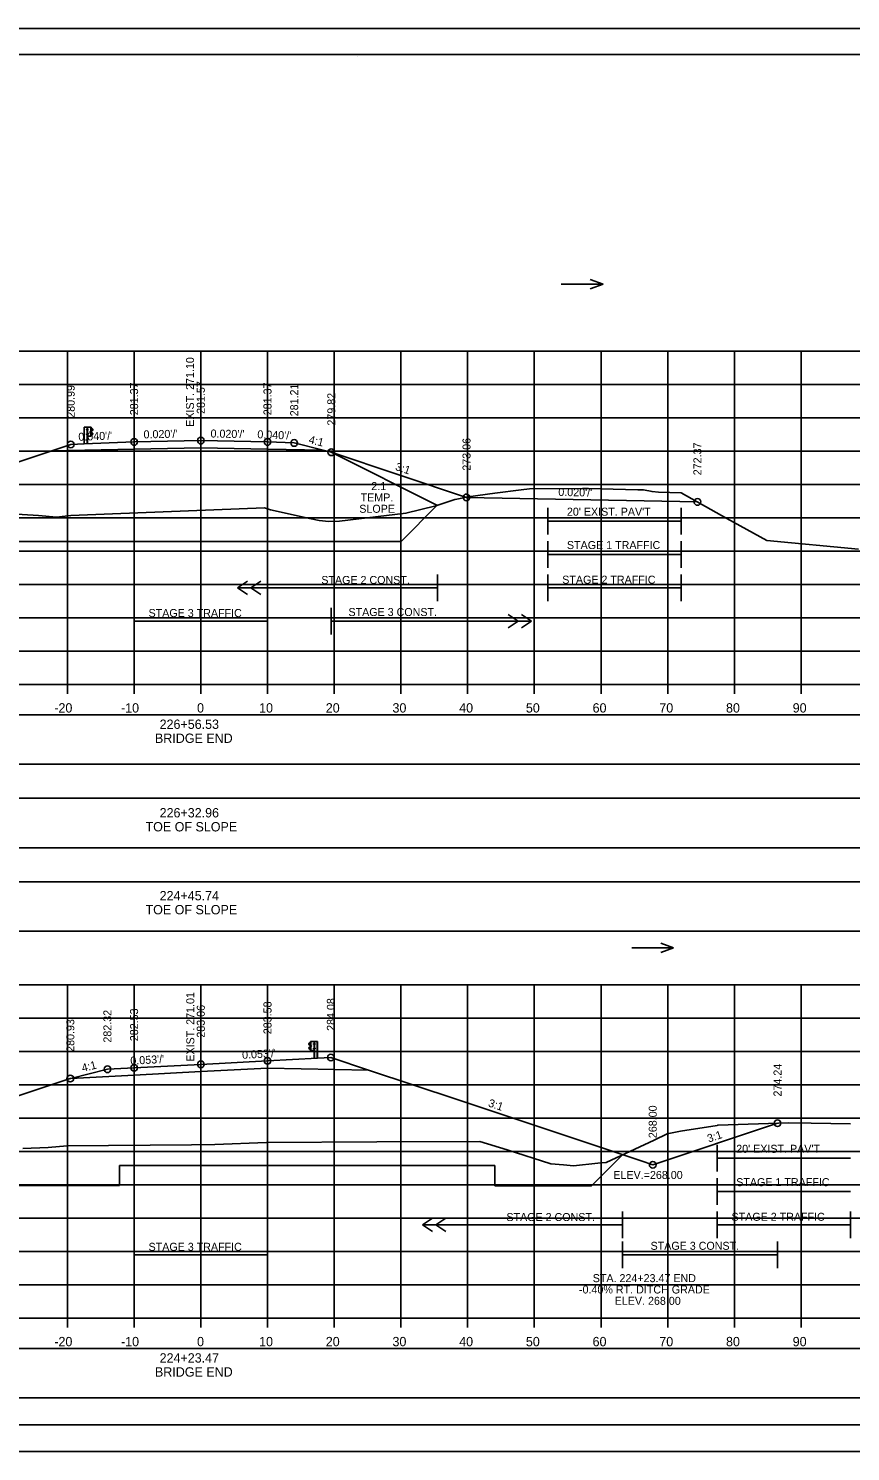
# Model space of a CAD drawing. Extents: x 4667 to 1632277, y -2100 to 724501.
# Drawn here: x 5751.3 to 5874.6, y -43.7 to 169.6 of the extents above; entities that cross this region are included whole.
import ezdxf

# ---------------------------------------------------------------- set-up
doc = ezdxf.new("R2010")
doc.units = 0
for name, color, linetype in [('R_Alt Surface', 7, 'Continuous'), ('R_Axis', 7, 'Continuous'), ('R_Axis Annot', 7, 'Continuous'), ('R_Border', 7, 'Continuous'), ('R_Border Notes', 7, 'Continuous'), ('R_Detour', 7, 'Continuous'), ('R_Draft', 7, 'Continuous'), ('R_Exist Surface', 7, 'Continuous'), ('R_Fin Surface', 7, 'Continuous'), ('R_Fin Surface Annot', 7, 'Continuous'), ('R_Grid', 7, 'Continuous'), ('R_No Plot', 7, 'Continuous'), ('R_Proposed CofA', 7, 'Continuous'), ('R_ROW', 7, 'Continuous'), ('R_Temp Easement', 7, 'Continuous'), ('R_Water Annot', 7, 'Continuous')]:
    doc.layers.add(name, color=color, linetype=linetype)

msp = doc.modelspace()

# ---------------------------------------------------------------- linework, layer by layer
at = {"layer": 'R_Alt Surface'}
for points in [[(5754.83, 106.3), (5767.18, 106.54), (5777.18, 106.74), (5787.18, 106.54), (5795.55, 106.38)], [(5757.7, 12.21), (5767.18, 12.71), (5777.18, 13.23), (5787.18, 13.76), (5802.34, 13.46)]]:
    msp.add_lwpolyline(points, dxfattribs=at)
at = {"layer": 'R_Axis'}
for p, q in [((5667.18, 71.26), (5947.18, 71.26)), ((5757.18, 69.86), (5757.18, 71.26)), ((5767.18, 69.86), (5767.18, 71.26)), ((5777.18, 69.86), (5777.18, 71.26)), ((5787.18, 69.86), (5787.18, 71.26)), ((5797.18, 69.86), (5797.18, 71.26)), ((5807.18, 69.86), (5807.18, 71.26)), ((5817.18, 69.86), (5817.18, 71.26)), ((5827.18, 69.86), (5827.18, 71.26)), ((5837.18, 69.86), (5837.18, 71.26)), ((5847.18, 69.86), (5847.18, 71.26)), ((5857.18, 69.86), (5857.18, 71.26)), ((5867.18, 69.86), (5867.18, 71.26)), ((5667.18, -23.74), (5947.18, -23.74)), ((5757.18, -25.14), (5757.18, -23.74)), ((5767.18, -25.14), (5767.18, -23.74)), ((5777.18, -25.14), (5777.18, -23.74)), ((5787.18, -25.14), (5787.18, -23.74)), ((5797.18, -25.14), (5797.18, -23.74)), ((5807.18, -25.14), (5807.18, -23.74)), ((5817.18, -25.14), (5817.18, -23.74)), ((5827.18, -25.14), (5827.18, -23.74)), ((5837.18, -25.14), (5837.18, -23.74)), ((5847.18, -25.14), (5847.18, -23.74)), ((5857.18, -25.14), (5857.18, -23.74)), ((5867.18, -25.14), (5867.18, -23.74))]:
    msp.add_line(p, q, dxfattribs=at)
at = {"layer": 'R_Border'}
for p, q in [((5648.18, 165.72), (5964.36, 165.72)), ((5800.7, 165.46), (5800.7, 165.46)), ((5800.7, 165.46), (5800.7, 165.46)), ((5964.36, -39.74), (5648.18, -39.74))]:
    msp.add_line(p, q, dxfattribs=at)
at = {"layer": 'R_Detour'}
msp.add_line((5796.75, 106.08), (5812.67, 98.12), dxfattribs=at)
at = {"layer": 'R_Draft'}
for p, q in [((5759.68, 109.84), (5759.68, 107.33)), ((5759.71, 109.84), (5759.71, 107.33)), ((5760.07, 108.74), (5760.07, 108.84)), ((5760.08, 109.43), (5760.08, 109.53)), ((5760.13, 108.85), (5760.08, 108.85)), ((5760.13, 108.82), (5760.08, 108.82)), ((5760.14, 109.54), (5760.09, 109.54)), ((5760.14, 109.51), (5760.09, 109.51)), ((5760.14, 109.45), (5760.09, 109.45)), ((5760.14, 109.42), (5760.09, 109.42)), ((5760.14, 109.45), (5760.1, 109.45)), ((5760.13, 108.73), (5760.13, 108.85)), ((5760.21, 109.84), (5760.14, 109.84)), ((5760.14, 109.42), (5760.14, 109.54)), ((5760.18, 107.33), (5760.18, 109.84)), ((5760.21, 109.84), (5760.2, 109.84)), ((5760.26, 109.47), (5760.21, 109.47)), ((5760.22, 109.54), (5760.27, 109.54)), ((5760.22, 109.41), (5760.27, 109.41)), ((5760.27, 108.85), (5760.22, 108.85)), ((5760.27, 109.54), (5760.27, 109.41)), ((5760.27, 108.73), (5760.27, 108.85)), ((5760.64, 109.11), (5760.64, 109.21)), ((5760.7, 109.22), (5760.65, 109.22)), ((5760.7, 109.19), (5760.65, 109.19)), ((5760.7, 109.13), (5760.65, 109.13)), ((5760.7, 109.13), (5760.65, 109.13)), ((5760.7, 109.1), (5760.65, 109.1)), ((5760.7, 109.1), (5760.7, 109.22)), ((5760.71, 108.48), (5760.71, 109.84)), ((5760.85, 109.63), (5760.74, 109.69)), ((5760.84, 109.61), (5760.75, 109.66)), ((5760.75, 109.1), (5760.75, 109.23)), ((5760.77, 109.1), (5760.77, 109.23)), ((5760.79, 109.3), (5760.97, 109.4)), ((5760.94, 108.92), (5760.79, 109.02)), ((5760.96, 108.94), (5760.8, 109.04)), ((5760.81, 109.28), (5760.98, 109.38)), ((5760.97, 109.51), (5760.84, 109.61)), ((5760.98, 109.52), (5760.85, 109.63)), ((5760.13, 108.76), (5760.08, 108.76)), ((5760.13, 108.73), (5760.08, 108.73)), ((5760.13, 108.76), (5760.09, 108.76)), ((5760.21, 108.48), (5760.17, 108.48)), ((5760.26, 108.79), (5760.21, 108.79)), ((5760.27, 108.73), (5760.22, 108.73)), ((5760.74, 108.64), (5760.84, 108.69)), ((5760.74, 108.62), (5760.86, 108.68)), ((5760.84, 108.69), (5760.97, 108.8)), ((5760.86, 108.68), (5760.98, 108.79)), ((5793.39, 17.43), (5793.52, 17.54)), ((5793.56, 17.18), (5793.39, 17.29)), ((5793.4, 17.42), (5793.53, 17.52)), ((5793.57, 17.21), (5793.4, 17.31)), ((5793.52, 17.54), (5793.63, 17.6)), ((5793.53, 17.52), (5793.62, 17.57)), ((5793.6, 17), (5793.6, 17.14)), ((5793.62, 17.01), (5793.62, 17.14)), ((5793.66, 16.39), (5793.66, 17.75)), ((5793.67, 17), (5793.67, 17.13)), ((5793.67, 17.13), (5793.72, 17.13)), ((5793.67, 17.1), (5793.72, 17.1)), ((5793.73, 17.02), (5793.73, 17.11)), ((5794.15, 17.45), (5794.1, 17.45)), ((5794.1, 17.45), (5794.1, 17.32)), ((5794.1, 17.38), (5794.16, 17.38)), ((5794.15, 17.32), (5794.1, 17.32)), ((5794.16, 17.75), (5794.17, 17.75)), ((5794.16, 17.75), (5794.23, 17.75)), ((5794.19, 15.24), (5794.19, 17.75)), ((5794.23, 17.33), (5794.23, 17.45)), ((5794.23, 17.45), (5794.28, 17.45)), ((5794.23, 17.42), (5794.28, 17.42)), ((5794.23, 17.36), (5794.27, 17.36)), ((5794.23, 17.36), (5794.28, 17.36)), ((5794.23, 17.33), (5794.28, 17.33)), ((5794.28, 17.34), (5794.28, 17.44)), ((5794.65, 17.75), (5794.65, 15.24)), ((5794.68, 17.75), (5794.68, 15.24)), ((5793.51, 16.59), (5793.38, 16.7)), ((5793.52, 16.6), (5793.4, 16.71)), ((5793.41, 16.85), (5793.57, 16.95)), ((5793.42, 16.83), (5793.58, 16.93)), ((5793.62, 16.53), (5793.51, 16.59)), ((5793.63, 16.55), (5793.52, 16.6)), ((5793.67, 17.03), (5793.72, 17.03)), ((5793.67, 17.03), (5793.72, 17.03)), ((5793.67, 17), (5793.72, 17)), ((5794.1, 16.64), (5794.1, 16.76)), ((5794.1, 16.76), (5794.15, 16.76)), ((5794.1, 16.7), (5794.16, 16.7)), ((5794.1, 16.64), (5794.15, 16.64)), ((5794.16, 16.39), (5794.19, 16.39)), ((5794.24, 16.64), (5794.24, 16.76)), ((5794.24, 16.76), (5794.29, 16.76)), ((5794.24, 16.73), (5794.29, 16.73)), ((5794.24, 16.67), (5794.28, 16.67)), ((5794.24, 16.67), (5794.29, 16.67)), ((5794.24, 16.64), (5794.29, 16.64)), ((5794.29, 16.65), (5794.29, 16.75))]:
    msp.add_line(p, q, dxfattribs=at)
for points in [[(5759.68, 109.84), (5760.14, 109.84), (5760.14, 107.33)], [(5794.68, 17.75), (5794.23, 17.75), (5794.23, 15.24)]]:
    msp.add_lwpolyline(points, dxfattribs=at)
for points in [[(5760.07, 108.82), (5760.07, 108.76), (5760.05, 108.76), (5760.05, 108.82)], [(5760.08, 109.51), (5760.08, 109.45), (5760.06, 109.45), (5760.06, 109.51)], [(5760.13, 108.87), (5760.13, 108.7), (5760.14, 108.7), (5760.14, 108.87)], [(5760.14, 109.56), (5760.14, 109.39), (5760.15, 109.39), (5760.15, 109.56)], [(5760.73, 109.84), (5760.73, 108.48), (5760.21, 108.48), (5760.21, 109.84)], [(5760.26, 109.54), (5760.26, 109.41), (5760.21, 109.41), (5760.21, 109.54)], [(5760.26, 108.85), (5760.26, 108.73), (5760.21, 108.73), (5760.21, 108.85)], [(5760.64, 109.19), (5760.64, 109.13), (5760.61, 109.13), (5760.61, 109.19)], [(5760.69, 109.24), (5760.69, 109.07), (5760.7, 109.07), (5760.7, 109.24)], [(5793.63, 17.75), (5793.64, 16.39), (5794.16, 16.39), (5794.16, 17.75)], [(5793.67, 17.15), (5793.67, 16.98), (5793.66, 16.98), (5793.66, 17.15)], [(5793.73, 17.1), (5793.73, 17.04), (5793.76, 17.04), (5793.76, 17.1)], [(5794.1, 17.45), (5794.1, 17.32), (5794.16, 17.32), (5794.16, 17.45)], [(5794.23, 17.47), (5794.23, 17.3), (5794.22, 17.3), (5794.22, 17.47)], [(5794.29, 17.42), (5794.29, 17.36), (5794.31, 17.36), (5794.31, 17.42)], [(5794.1, 16.76), (5794.1, 16.64), (5794.16, 16.64), (5794.16, 16.76)], [(5794.24, 16.78), (5794.24, 16.61), (5794.23, 16.61), (5794.23, 16.78)], [(5794.3, 16.73), (5794.3, 16.67), (5794.32, 16.67), (5794.32, 16.73)]]:
    msp.add_lwpolyline(points, close=True, dxfattribs=at)
for centre, radius, start, end in [((5760.1, 108.84), 0.022, 134.5745, 222.2244), ((5760.17, 108.79), 0.0922, 159.7423, 200.2577), ((5760.11, 109.53), 0.022, 134.5745, 222.2244), ((5760.18, 109.48), 0.0922, 159.7423, 200.2577), ((5760.11, 109.43), 0.025, 140.9334, 216.6234), ((5760.66, 109.2), 0.022, 134.5745, 222.2244), ((5760.73, 109.16), 0.0922, 159.7423, 200.2577), ((5760.67, 109.11), 0.025, 140.9334, 216.6234), ((5760.84, 109.22), 0.0865, 118.106, 175.0444), ((5760.82, 109.09), 0.0703, 171.7804, 246.8536), ((5760.84, 109.22), 0.0622, 118.106, 175.0444), ((5760.77, 109.15), 0.0453, 282.9554, 86.0697), ((5760.82, 109.09), 0.0462, 171.7804, 246.8536), ((5760.9, 108.85), 0.0854, 325.2184, 59.12), ((5760.9, 108.85), 0.109, 325.2184, 59.12), ((5760.94, 109.46), 0.062, 299.2499, 57.9783), ((5760.94, 109.46), 0.0856, 299.2499, 57.9783), ((5760.1, 108.74), 0.025, 140.9334, 216.6234), ((5793.43, 17.36), 0.0856, 122.0217, 240.7501), ((5793.43, 17.36), 0.062, 122.0217, 240.7501), ((5793.53, 17.13), 0.0622, 4.9556, 61.894), ((5793.6, 17.06), 0.0453, 93.9303, 257.0446), ((5793.53, 17.13), 0.0865, 4.9556, 61.894), ((5793.71, 17.11), 0.022, 317.7756, 45.4255), ((5793.64, 17.07), 0.0922, 339.7423, 20.2577), ((5794.26, 17.44), 0.022, 317.7756, 45.4255), ((5794.19, 17.39), 0.0922, 339.7423, 20.2577), ((5794.26, 17.34), 0.025, 323.3766, 39.0666), ((5793.47, 16.76), 0.109, 120.88, 214.7816), ((5793.47, 16.76), 0.0854, 120.88, 214.7816), ((5793.55, 17), 0.0462, 293.1464, 8.2196), ((5793.55, 17), 0.0703, 293.1464, 8.2196), ((5793.7, 17.02), 0.025, 323.3766, 39.0666), ((5794.27, 16.75), 0.022, 317.7756, 45.4255), ((5794.2, 16.7), 0.0922, 339.7423, 20.2577), ((5794.27, 16.65), 0.025, 323.3766, 39.0666)]:
    msp.add_arc(centre, radius, start, end, dxfattribs=at)
at = {"layer": 'R_Exist Surface'}
for points in [[(5731.49, 97.92), (5752.87, 96.58), (5755.53, 96.37), (5757.69, 96.58), (5763.96, 96.85), (5786.71, 97.74), (5787.61, 97.45), (5793.73, 96.11), (5794.95, 95.85), (5796.38, 95.7), (5797.99, 95.75), (5807.93, 96.95), (5812.43, 98.06), (5815.25, 98.98), (5815.34, 99.02), (5817.26, 99.38), (5821.26, 99.94), (5825.21, 100.46), (5826.45, 100.62), (5834.4, 100.66), (5835.3, 100.67), (5842.7, 100.47), (5843.54, 100.45), (5844.83, 100.18), (5845.79, 100.12), (5849.21, 99.98), (5856.04, 96.15), (5862.02, 92.84), (5875.77, 91.57)], [(5750.5, 1.69), (5754.32, 1.84), (5757.13, 2.09), (5775.77, 2.25), (5779.3, 2.29), (5787.05, 2.59), (5803.57, 2.69), (5819.02, 2.77), (5823.12, 1.53), (5829.67, -0.57), (5831.58, -0.72), (5833.08, -0.9), (5836.68, -0.47), (5837.95, -0.37), (5845.15, 2.95), (5847.11, 3.92), (5849.12, 4.28), (5854.57, 5.16), (5854.66, 5.18), (5854.66, 5.18), (5854.73, 5.18), (5865.27, 5.56), (5868.67, 5.5), (5874.59, 5.4)]]:
    msp.add_lwpolyline(points, dxfattribs=at)
at = {"layer": 'R_Fin Surface'}
for points in [[(5729.97, 98.01), (5754.83, 106.3), (5757.68, 107.25), (5759.68, 107.33), (5767.18, 107.63), (5777.18, 107.83), (5787.18, 107.63), (5791.18, 107.47), (5795.55, 106.38), (5796.75, 106.08), (5817.02, 99.32), (5851.63, 98.63)], [(5709.82, -3.74), (5726.62, 1.87), (5757.62, 12.19), (5757.7, 12.21), (5763.18, 13.58), (5767.18, 13.79), (5777.18, 14.32), (5787.18, 14.84), (5794.68, 15.24), (5796.68, 15.34), (5802.34, 13.46), (5815.75, 8.99), (5827.46, 5.08), (5843.2, -0.16), (5844.93, -0.74), (5863.64, 5.5)]]:
    msp.add_lwpolyline(points, dxfattribs=at)
at = {"layer": 'R_Grid'}
for p, q in [((5667.18, 121.26), (5947.18, 121.26)), ((5757.18, 71.26), (5757.18, 121.26)), ((5767.18, 71.26), (5767.18, 121.26)), ((5777.18, 71.26), (5777.18, 121.26)), ((5787.18, 71.26), (5787.18, 121.26)), ((5797.18, 71.26), (5797.18, 121.26)), ((5807.18, 71.26), (5807.18, 121.26)), ((5817.18, 71.26), (5817.18, 121.26)), ((5827.18, 71.26), (5827.18, 121.26)), ((5837.18, 71.26), (5837.18, 121.26)), ((5847.18, 71.26), (5847.18, 121.26)), ((5857.18, 71.26), (5857.18, 121.26)), ((5867.18, 71.26), (5867.18, 121.26)), ((5667.18, 116.26), (5947.18, 116.26)), ((5667.18, 111.26), (5947.18, 111.26)), ((5667.18, 106.26), (5947.18, 106.26)), ((5667.18, 101.26), (5947.18, 101.26)), ((5667.18, 96.26), (5947.18, 96.26)), ((5667.18, 91.26), (5947.18, 91.26)), ((5667.18, 86.26), (5947.18, 86.26)), ((5667.18, 81.26), (5947.18, 81.26)), ((5667.18, 76.26), (5947.18, 76.26)), ((5667.18, 71.26), (5947.18, 71.26)), ((5667.18, 26.26), (5947.18, 26.26)), ((5757.18, -23.74), (5757.18, 26.26)), ((5767.18, -23.74), (5767.18, 26.26)), ((5777.18, -23.74), (5777.18, 26.26)), ((5787.18, -23.74), (5787.18, 26.26)), ((5797.18, -23.74), (5797.18, 26.26)), ((5807.18, -23.74), (5807.18, 26.26)), ((5817.18, -23.74), (5817.18, 26.26)), ((5827.18, -23.74), (5827.18, 26.26)), ((5837.18, -23.74), (5837.18, 26.26)), ((5847.18, -23.74), (5847.18, 26.26)), ((5857.18, -23.74), (5857.18, 26.26)), ((5867.18, -23.74), (5867.18, 26.26)), ((5667.18, 21.26), (5947.18, 21.26)), ((5667.18, 16.26), (5947.18, 16.26)), ((5667.18, 11.26), (5947.18, 11.26)), ((5667.18, 6.26), (5947.18, 6.26)), ((5667.18, 1.26), (5947.18, 1.26)), ((5667.18, -3.74), (5947.18, -3.74)), ((5667.18, -8.74), (5947.18, -8.74)), ((5667.18, -13.74), (5947.18, -13.74)), ((5667.18, -18.74), (5947.18, -18.74)), ((5667.18, -23.74), (5947.18, -23.74))]:
    msp.add_line(p, q, dxfattribs=at)
at = {"layer": 'R_No Plot'}
for p, q in [((5635.78, 169.61), (5969.12, 169.61)), ((5635.78, -43.72), (5969.12, -43.72))]:
    msp.add_line(p, q, dxfattribs=at)
for points in [[(5635.78, 169.61), (5969.12, 169.61), (5969.12, -43.72), (5635.78, -43.72)], [(5882.1, 165.72), (5901.72, 165.72), (5901.72, 155.84), (5917.84, 155.84), (5941.04, 155.84), (5941.04, 131.51), (5964.36, 131.51), (5964.36, -39.74), (5648.18, -39.74), (5648.18, 165.72)]]:
    msp.add_lwpolyline(points, close=True, dxfattribs=at)
for centre in [(5757.68, 107.25), (5757.68, 107.25), (5767.18, 107.63), (5777.18, 107.83), (5787.18, 107.63), (5791.18, 107.47), (5796.75, 106.08), (5817.02, 99.32), (5851.63, 98.63), (5787.18, 14.84), (5796.68, 15.34), (5796.68, 15.34), (5763.18, 13.58), (5767.18, 13.79), (5777.18, 14.32), (5757.62, 12.19), (5863.64, 5.5), (5844.93, -0.74)]:
    msp.add_circle(centre, 0.5, dxfattribs=at)
at = {"layer": 'R_Proposed CofA'}
for p, q in [((5782.67, 85.77), (5784.17, 86.77)), ((5782.67, 85.77), (5784.17, 84.77)), ((5784.67, 85.77), (5786.17, 86.77)), ((5784.67, 85.77), (5786.17, 84.77)), ((5824.75, 80.77), (5823.25, 81.77)), ((5826.75, 80.77), (5825.25, 81.77)), ((5824.75, 80.77), (5823.25, 79.77)), ((5826.75, 80.77), (5825.25, 79.77)), ((5810.41, -9.74), (5811.91, -8.74)), ((5810.41, -9.74), (5811.91, -10.74)), ((5812.41, -9.74), (5813.91, -8.74)), ((5812.41, -9.74), (5813.91, -10.74))]:
    msp.add_line(p, q, dxfattribs=at)
for points in [[(5667.23, 59.32), (5947.13, 59.32), (5947.13, 66.74), (5667.23, 66.74)], [(5667.23, 46.79), (5947.13, 46.79), (5947.13, 54.21), (5667.23, 54.21)], [(5667.23, 34.27), (5947.13, 34.27), (5947.13, 41.69), (5667.23, 41.69)], [(5667.23, -35.68), (5947.13, -35.68), (5947.13, -28.26), (5667.23, -28.26)]]:
    msp.add_lwpolyline(points, close=True, dxfattribs=at)
at = {"layer": 'R_ROW'}
for p, q in [((5812.64, 98.13), (5807.21, 92.7)), ((5735.29, 92.7), (5807.21, 92.7)), ((5840.41, 0.77), (5835.74, -3.9)), ((5764.97, -0.85), (5764.97, -3.85)), ((5764.97, -0.85), (5821.26, -0.85)), ((5821.26, -3.9), (5821.26, -0.85)), ((5738.5, -3.85), (5764.97, -3.85)), ((5821.26, -3.9), (5835.74, -3.9))]:
    msp.add_line(p, q, dxfattribs=at)
at = {"layer": 'R_Temp Easement'}
for p, q in [((5829.21, 93.77), (5829.21, 97.77)), ((5849.21, 93.77), (5849.21, 97.77)), ((5829.21, 95.77), (5849.21, 95.77)), ((5829.21, 88.77), (5829.21, 92.77)), ((5849.21, 88.77), (5849.21, 92.77)), ((5829.21, 90.77), (5849.21, 90.77)), ((5812.67, 83.77), (5812.67, 87.77)), ((5829.21, 83.77), (5829.21, 87.77)), ((5849.21, 83.77), (5849.21, 87.77)), ((5812.67, 85.77), (5782.67, 85.77)), ((5849.21, 85.77), (5829.21, 85.77)), ((5767.18, 78.77), (5767.18, 82.77)), ((5787.18, 78.77), (5787.18, 82.77)), ((5796.75, 78.77), (5796.75, 82.77)), ((5787.18, 80.77), (5767.18, 80.77)), ((5796.75, 80.77), (5826.75, 80.77)), ((5854.59, -1.74), (5854.59, 2.26)), ((5854.59, 0.26), (5874.59, 0.26)), ((5854.59, -6.74), (5854.59, -2.74)), ((5854.59, -4.74), (5874.59, -4.74)), ((5840.41, -11.74), (5840.41, -7.74)), ((5854.59, -11.74), (5854.59, -7.74)), ((5874.59, -11.74), (5874.59, -7.74)), ((5840.41, -9.74), (5810.41, -9.74)), ((5874.59, -9.74), (5854.59, -9.74)), ((5767.18, -16.24), (5767.18, -12.24)), ((5787.18, -16.24), (5787.18, -12.24)), ((5840.41, -16.24), (5840.41, -12.24)), ((5863.64, -16.24), (5863.64, -12.24)), ((5787.18, -14.24), (5767.18, -14.24)), ((5840.41, -14.24), (5863.64, -14.24))]:
    msp.add_line(p, q, dxfattribs=at)
at = {"layer": 'R_Water Annot'}
for p, q in [((5831.2, 131.26), (5837.49, 131.26)), ((5837.49, 131.26), (5835.56, 131.96)), ((5837.49, 131.26), (5835.56, 130.56)), ((5848.07, 31.79), (5846.15, 32.49)), ((5841.79, 31.79), (5848.07, 31.79)), ((5848.07, 31.79), (5846.15, 31.09))]:
    msp.add_line(p, q, dxfattribs=at)

# ---------------------------------------------------------------- texts
at = {"layer": 'R_Axis Annot'}
for s, p in [('-20', (5755.22, 67.06)), ('-10', (5765.22, 67.06)), ('0', (5776.62, 67.06)), ('10', (5785.92, 67.06)), ('20', (5795.92, 67.06)), ('30', (5805.92, 67.06)), ('40', (5815.92, 67.06)), ('50', (5825.92, 67.06)), ('60', (5835.92, 67.06)), ('70', (5845.92, 67.06)), ('80', (5855.92, 67.06)), ('90', (5865.92, 67.06)), ('226+56.53', (5771.01, 64.61)), ('BRIDGE END', (5770.31, 62.51)), ('226+32.96', (5771.01, 51.34)), ('TOE OF SLOPE', (5768.9, 49.24)), ('224+45.74', (5771.01, 38.91)), ('TOE OF SLOPE', (5768.9, 36.81)), ('-20', (5755.22, -27.94)), ('-10', (5765.22, -27.94)), ('0', (5776.62, -27.94)), ('10', (5785.92, -27.94)), ('20', (5795.92, -27.94)), ('30', (5805.92, -27.94)), ('40', (5815.92, -27.94)), ('50', (5825.92, -27.94)), ('60', (5835.92, -27.94)), ('70', (5845.92, -27.94)), ('80', (5855.92, -27.94)), ('90', (5865.92, -27.94)), ('224+23.47', (5771.01, -30.39)), ('BRIDGE END', (5770.31, -32.49))]:
    msp.add_text(s, height=1.4, dxfattribs=at).set_placement(p)
at = {"layer": 'R_Border Notes'}
for s, p in [('2:1', (5802.74, 100.41)), ('SLOPE', (5800.94, 97.01)), ('TEMP.', (5801.14, 98.71))]:
    msp.add_text(s, height=1.2, dxfattribs=at).set_placement(p)
at = {"layer": 'R_Fin Surface Annot'}
for s, rotation, p in [('280.99', 90, (5758.28, 111.25)), ('281.37', 90, (5767.78, 111.63)), ('281.57', 90, (5777.78, 111.83)), ('281.37', 90, (5787.78, 111.63)), ('281.21', 90, (5791.78, 111.47)), ('279.82', 90, (5797.35, 110.08)), ("0.040'/'", 2.2906, (5758.85, 107.79)), ("0.020'/'", 1.1458, (5768.61, 108.16)), ("0.020'/'", 358.8542, (5778.63, 108.3)), ("0.040'/'", 357.7094, (5785.64, 108.19)), ('4:1', 345.9638, (5793.28, 107.46)), ('273.06', 90, (5817.62, 103.32)), ('272.37', 90, (5852.23, 102.63)), ('3:1', 341.5651, (5806.25, 103.44)), ("0.020'/'", 358.8542, (5830.77, 99.54)), ('283.58', 90, (5787.78, 18.84)), ('284.08', 90, (5797.28, 19.34)), ('282.32', 90, (5763.78, 17.58)), ('282.53', 90, (5767.78, 17.79)), ('283.06', 90, (5777.78, 18.32)), ('280.93', 90, (5758.22, 16.19)), ("0.053'/'", 3.0066, (5766.65, 14.26)), ("0.053'/'", 3.0066, (5783.4, 15.14)), ('4:1', 14.0362, (5759.48, 13.17)), ('274.24', 90, (5864.24, 9.5)), ('3:1', 341.5651, (5820.18, 8.04)), ('268.00', 90, (5845.53, 3.26)), ('3:1', 18.4349, (5853.34, 2.59))]:
    msp.add_text(s, height=1.2, rotation=rotation, dxfattribs=at).set_placement(p)
at = {"layer": 'R_Temp Easement'}
for s, p in [('EXIST. 271.10', (5776.16, 109.9)), ('EXIST. 271.01', (5776.21, 14.72))]:
    msp.add_text(s, height=1.2, rotation=90, dxfattribs=at).set_placement(p)
for s, height, p in [("20' EXIST. PAV'T", 1.2, (5832.07, 96.57)), ('STAGE 1 TRAFFIC', 1.2, (5832.07, 91.57)), ('STAGE 2 CONST.', 1.1985, (5795.25, 86.34)), ('STAGE 2 TRAFFIC', 1.1985, (5831.37, 86.38)), ('STAGE 3 TRAFFIC', 1.1985, (5769.35, 81.38)), ('STAGE 3 CONST.', 1.1985, (5799.32, 81.53)), ("20' EXIST. PAV'T", 1.2, (5857.45, 1.06)), ('STAGE 1 TRAFFIC', 1.2, (5857.45, -3.94)), ('STAGE 2 CONST.', 1.1985, (5823, -9.17)), ('STAGE 2 TRAFFIC', 1.1985, (5856.75, -9.13)), ('STAGE 3 TRAFFIC', 1.1985, (5769.35, -13.63)), ('STAGE 3 CONST.', 1.1985, (5844.61, -13.48))]:
    msp.add_text(s, height=height, dxfattribs=at).set_placement(p)
at = {"layer": 'R_Water Annot'}
for s, p in [('ELEV.=268.00', (5839.03, -2.86)), ('-0.40% RT. DITCH GRADE', (5833.88, -20.03)), ('STA. 224+23.47 END', (5835.94, -18.33)), ('ELEV. 268.00', (5839.23, -21.73))]:
    msp.add_text(s, height=1.2, dxfattribs=at).set_placement(p)

doc.saveas('drawing.dxf')
